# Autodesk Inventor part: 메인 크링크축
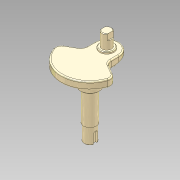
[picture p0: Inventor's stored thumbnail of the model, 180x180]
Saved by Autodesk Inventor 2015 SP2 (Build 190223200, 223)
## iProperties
Manager: KYOUNG IL JANG
Company: 한국ATC센터
Created: 2012-10
Part Number: 메인 크링크축
Document SubType Name: Modeling
Density: 1 g/cm^3
Checked By: KYOUNG IL JANG
Vendor: CBT Solutions
Designer: KYOUNG IL JANG
Material: 일반
Appearance: _시험_금속-티타늄(광택)
크링크폭: 19.000 mm
크랭크길이: 18.000 mm
크랭키위치: 65.000 mm
무게추: 90.000 mm
크랭크각도높이: 21.000 mm
크링크각도: -15.00 deg
Author: KYOUNG IL JANG
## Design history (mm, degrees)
sketch "스케치1"
  geometry: L1 (-19, 109.368)-(-19, 91.368); L2 (-19, 91.368)-(-44.545, 76.619); L3 (19, 109.368)-(19, 91.368); L4 (19, 91.368)-(44.545, 76.619); C1 r 32.5 at (0, 83) reference; C2 r 10 at (0, 83); C3 r 17.5 at (0, 83); A1 r 45 centre (0, 83) between (-44.545, 76.619) and (44.545, 76.619); A2 r 32.5 centre (0, 83) between (-19, 109.368) and (19, 109.368); A3 r 19 centre (0, 109.368) between (19, 109.368) and (-19, 109.368); 1 further point
  constraints: 8 end point, 6 point on circle, 5 centre point, 4 coincident, 2 equal length, 2 vertical alignment, 1 horizontal alignment, 1 parallel, 1 tangent, 1 vertical, 3 other
  dimensions: "d0" = 20 diameter of C2; "d1" = 35 diameter of C3; "d4" = 120 deg angle of L3 L4
  node "참조1"
extrude "돌출1" new body sketch "스케치1" distance "d7" = 12; taper "d8" = 0 deg
extrude "돌출2" join sketch "스케치1" distance "d9" = 5; taper "d10" = 0 deg
extrude "돌출3" join sketch "스케치1" distance "d11" = 100; taper "d12" = 0 deg
sketch "스케치2"
  geometry: C1 r 7.5 at (0, 109.368); C2 r 11 at (0, 109.368); A1 r 19 centre (0, 109.368) between (19, 109.368) and (-19, 109.368) reference; 1 further point
  constraints: 2 centre point, 2 coincident
  dimensions: "d13" = 15 diameter of C1; "d14" = 22 diameter of C2
extrude "돌출4" join sketch "스케치2" distance "d15" = 3; taper "d16" = 0 deg
extrude "돌출5" join sketch "스케치2" distance "d17" = 25; taper "d18" = 0 deg
node "작업 평면1"
sketch "스케치3"
  geometry: L1 (-5.75, 4.815)-(-5.75, -4.815); L2 (5.75, 4.815)-(5.75, -4.815); A1 r 7.5 centre (0, 0) between (-5.75, 4.815) and (-5.75, -4.815) reference; 1 further point
  constraints: 4 end point, 4 point on circle, 2 parallel, 1 vertical
  dimensions: "d20" = 11.5 distance between parallel lines of L2 L1
extrude "돌출6" cut sketch "스케치3" stored distance "d21" = 10; taper "d22" = 0 deg
sketch "스케치4"
  geometry: L1 (-19, 91.368)-(-19, 109.368) reference; L2 (19, 109.368)-(19, 91.368) reference; C1 r 17.5 at (0, 83) reference; 3 further points
  constraints: 2 point on line, 1 horizontal alignment, 1 other
node "작업 평면2"
  node "작업축1"
sketch "스케치5"
  geometry: L1 (0, 0)-(38, 0); L2 (38, 0)-(38, 50); L3 (38, 50)-(0, 50); L4 (0, 50)-(0, 0); L5 (38, 5.185)-(38, -12.202) reference; 2 further points
  constraints: 8 end point, 1 coincident, 1 collinear, 1 horizontal, 1 perpendicular
  dimensions: "d27" = 50 distance between parallel lines of L3 L1
extrude "돌출7" cut sketch "스케치5" stored distance "d28" = 10; taper "d29" = 0 deg
fillet "모깎기1" dims "d23" = 10, "d24" = 2
sketch "스케치6"
  geometry: C1 r 17.5 at (0, 0) reference; C2 r 15 at (0, 0); 1 further point
  constraints: 1 centre point, 1 coincident
  dimensions: "d30" = 30 diameter of C2
extrude "돌출8" join sketch "스케치6" distance "d31" = 21; taper "d32" = 0 deg
sketch "스케치7"
  geometry: C1 r 10 at (0, 0) reference; C2 r 9 at (0, 0); 1 further point
  constraints: 1 centre point, 1 coincident
  dimensions: "d33" = 1 radial gap between concentric circles of C1 C2
extrude "돌출9" cut sketch "스케치7" distance "d34" = 25; taper "d35" = 0 deg
node "작업 평면3"
sketch "스케치8"
  geometry: L1 (-9, 0)-(9, 0) reference; L2 (-3, 0)-(-3, 15); L3 (3, 15)-(3, 0); A1 r 3 centre (0, 15) between (3, 15) and (-3, 15); 2 further points
  constraints: 4 end point, 2 perpendicular, 2 point on circle, 2 point on line, 2 tangent, 1 centre point, 1 midpoint, 1 vertical alignment
  dimensions: "d36" = 6 distance between parallel lines of L3 L2; "d37" = 18 dimension on A1 L1
extrude "돌출10" cut sketch "스케치8" distance "d38" = 3.5; taper "d39" = 0 deg
chamfer "모따기1" distance "d40" = 1; stored, may be unused: second distance "d41" = 2, angle "d42" = 45 deg
node "솔리드1"
node "투영된 루프1"
other parameters: "d19" = 13
